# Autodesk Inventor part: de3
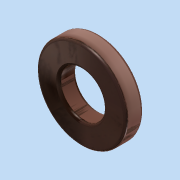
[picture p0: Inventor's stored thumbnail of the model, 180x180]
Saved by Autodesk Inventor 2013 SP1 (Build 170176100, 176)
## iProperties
Created: 2016-04
Part Number: de3
Material: Пластик АБС
Document SubType Name: Modeling
Designer: Кравец
Density: 1 g/cm^3
Author: Кравец
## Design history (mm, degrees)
sketch "Эскиз1"
  geometry: C1 r 2.5 at (0, 0); C2 r 5 at (0, 0); 1 further point
  constraints: 2 centre point, 2 coincident
  dimensions: "d0" = 5 diameter of C1; "d2" = 10 diameter of C2
extrude "Выдавливание1" new body sketch "Эскиз1" distance "d3" = 2; taper "d4" = 0 deg
fillet "Сопряжение1" dims "d5" = 0.3
node "Твердое тело1"
